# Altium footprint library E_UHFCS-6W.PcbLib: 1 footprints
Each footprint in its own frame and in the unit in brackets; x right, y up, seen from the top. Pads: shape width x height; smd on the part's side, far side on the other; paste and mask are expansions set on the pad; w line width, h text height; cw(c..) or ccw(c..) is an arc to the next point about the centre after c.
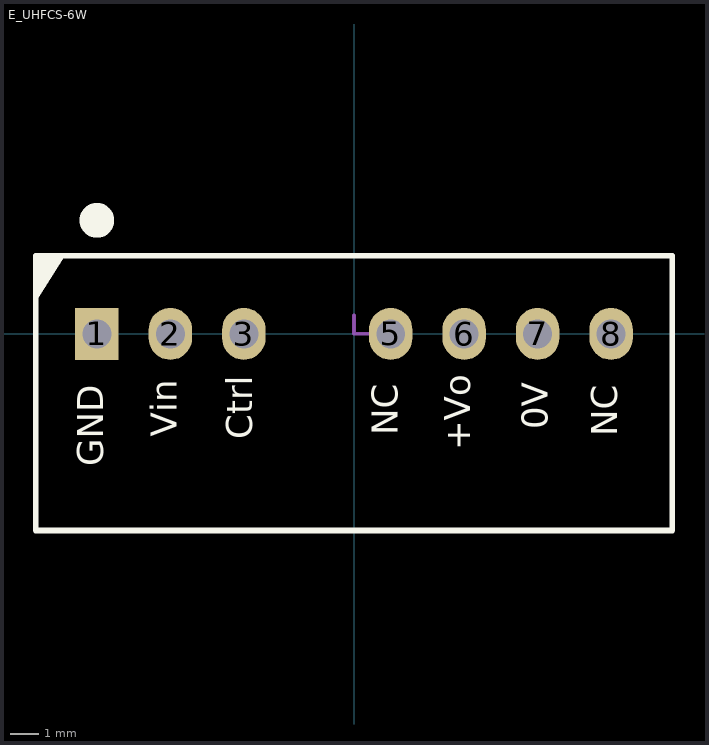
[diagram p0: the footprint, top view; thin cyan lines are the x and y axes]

## E_UHFCS-6W [mm]
height 12
pads (7):
  rect 1.5x1.8 hole 1: 1(-8.89,0)
  oval 1.5x1.8 hole 1: 2(-6.35,0) 3(-3.81,0) 5(1.27,0) 6(3.81,0) 7(6.35,0) 8(8.89,0)
Top Overlay:
  circle w1: c-8.89,3.925 r0.1
  region: -11,1.114 -11,2.7 -10.006,2.7
  lines w0.2: -11,-6.8 11,-6.8 11,2.7 -11,2.7 -11,-6.8
  text "NC" at 1.803,-3.502 h1.52
  text "Ctrl" at -3.226,-3.648 h1.52
  text "GND" at -8.382,-4.573 h1.52
  text "Vin" at -5.842,-3.563 h1.52
  text "+Vo" at 4.318,-4.031 h1.52
  text "0V" at 6.985,-3.291 h1.52
  text "NC" at 9.398,-3.538 h1.52
Mechanical 15:
  lines w0.127: 0,0.635 0,0 0.635,0
3D body: height 12, standoff 0, extent -10.93,-6.8 11,2.7
3D body "zhenjao01.stp": height 8.36, standoff -4.08, extent -9.59,-0.12 -8.19,1.48
3D body "zhenjao01.stp": height 8.36, standoff -4.08, extent -7.05,-0.12 -5.65,1.48
3D body "zhenjao01.stp": height 8.36, standoff -4.08, extent -4.51,-0.12 -3.11,1.48
3D body "zhenjao01.stp": height 8.36, standoff -4.08, extent 0.57,-0.12 1.97,1.48
3D body "zhenjao01.stp": height 8.36, standoff -4.08, extent 3.11,-0.12 4.51,1.48
3D body "zhenjao01.stp": height 8.36, standoff -4.08, extent 5.65,-0.12 7.05,1.48
3D body "zhenjao01.stp": height 8.36, standoff -4.08, extent 8.19,-0.12 9.59,1.48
